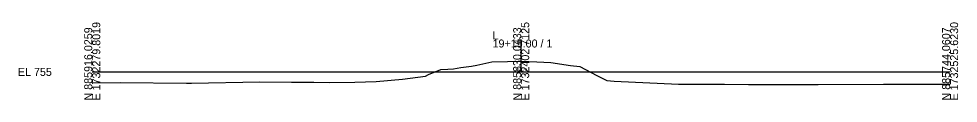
# Model space of a CAD drawing. Extents: x -173 to 6803, y -2990 to 11029.
# Drawn here: x 3874.3 to 4202.8, y 990.3 to 1017.3 of the extents above; entities that cross this region are included whole.
import ezdxf

# ---------------------------------------------------------------- set-up
doc = ezdxf.new("R2010")
doc.units = 0
for name, color, linetype in [('Default', 7, 'Continuous'), ('Exist Cross Section Cell', 7, 'Continuous'), ('Exist XS Center Line Elevation Label', 7, 'Continuous'), ('Exist XS Ground Line', 7, 'Continuous')]:
    doc.layers.add(name, color=color, linetype=linetype)

msp = doc.modelspace()

# ---------------------------------------------------------------- linework, layer by layer
at = {"layer": 'Exist Cross Section Cell'}
for p, q in [((4050, 1000), (4050, 1011.35)), ((3900, 1000), (4050, 1000)), ((4050, 1000), (4200, 1000))]:
    msp.add_line(p, q, dxfattribs=at)
at = {"layer": 'Exist XS Ground Line'}
msp.add_lwpolyline([(3900, 996.19), (3909.81, 996.29), (3933, 996.06), (3934.43, 996.05), (3934.74, 996.06), (3958.63, 996.55), (3969.63, 996.45), (3977.52, 996.41), (3983.03, 996.25), (3991.88, 996.39), (3999.29, 996.65), (4008.47, 997.49), (4016.54, 998.5), (4017.64, 999.05), (4021.89, 1000.84), (4024.32, 1000.99), (4026.32, 1001.05), (4028.94, 1001.49), (4032.66, 1002.01), (4034.45, 1002.39), (4039.75, 1003.54), (4045.25, 1003.66), (4049.84, 1003.76), (4055.51, 1003.51), (4060.35, 1003.31), (4067.21, 1002.25), (4070.52, 1001.85), (4076.44, 998.74), (4079.97, 997), (4082.52, 996.81), (4105.07, 995.7), (4109.2, 995.69), (4121.13, 995.69), (4129.48, 995.65), (4135.49, 995.65), (4144.05, 995.6), (4153.92, 995.56), (4176.73, 995.73), (4178.58, 995.74), (4178.98, 995.74), (4200, 995.76)], dxfattribs=at)

# ---------------------------------------------------------------- texts
at = {"layer": 'Default'}
msp.add_text('-', height=0.0001, dxfattribs=at).set_placement((3900, 1000))
at = {"layer": 'Exist Cross Section Cell'}
for s, p in [('N 885916.0259', (3900, 990)), ('E 1732279.8019', (3902.8, 990)), ('N 885830.0433', (4050, 990)), ('E 1732402.7125', (4052.8, 990)), ('N 885744.0607', (4200, 990)), ('E 1732525.6230', (4202.8, 990))]:
    msp.add_text(s, height=2.8, rotation=90, dxfattribs=at).set_placement(p)
for s, p in [('L', (4040, 1011.35)), ('19+15.00 / 1', (4040, 1008.55)), ('EL 755', (3874, 998.6))]:
    msp.add_text(s, height=2.8, dxfattribs=at).set_placement(p)
at = {"layer": 'Exist XS Center Line Elevation Label'}
msp.add_text('758.76', height=1, rotation=360, dxfattribs=at).set_placement((4047.92, 1000.33))

doc.saveas('drawing.dxf')
